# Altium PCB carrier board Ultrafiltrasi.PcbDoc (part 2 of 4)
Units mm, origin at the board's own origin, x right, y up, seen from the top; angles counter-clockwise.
Board outline 196.34 x 220.85 mm, 2 copper layers (Top Layer, Bottom Layer); 114 components, 209 nets, 667 pads, 70 vias.
Unrouted connection lines stored in the file: 5.
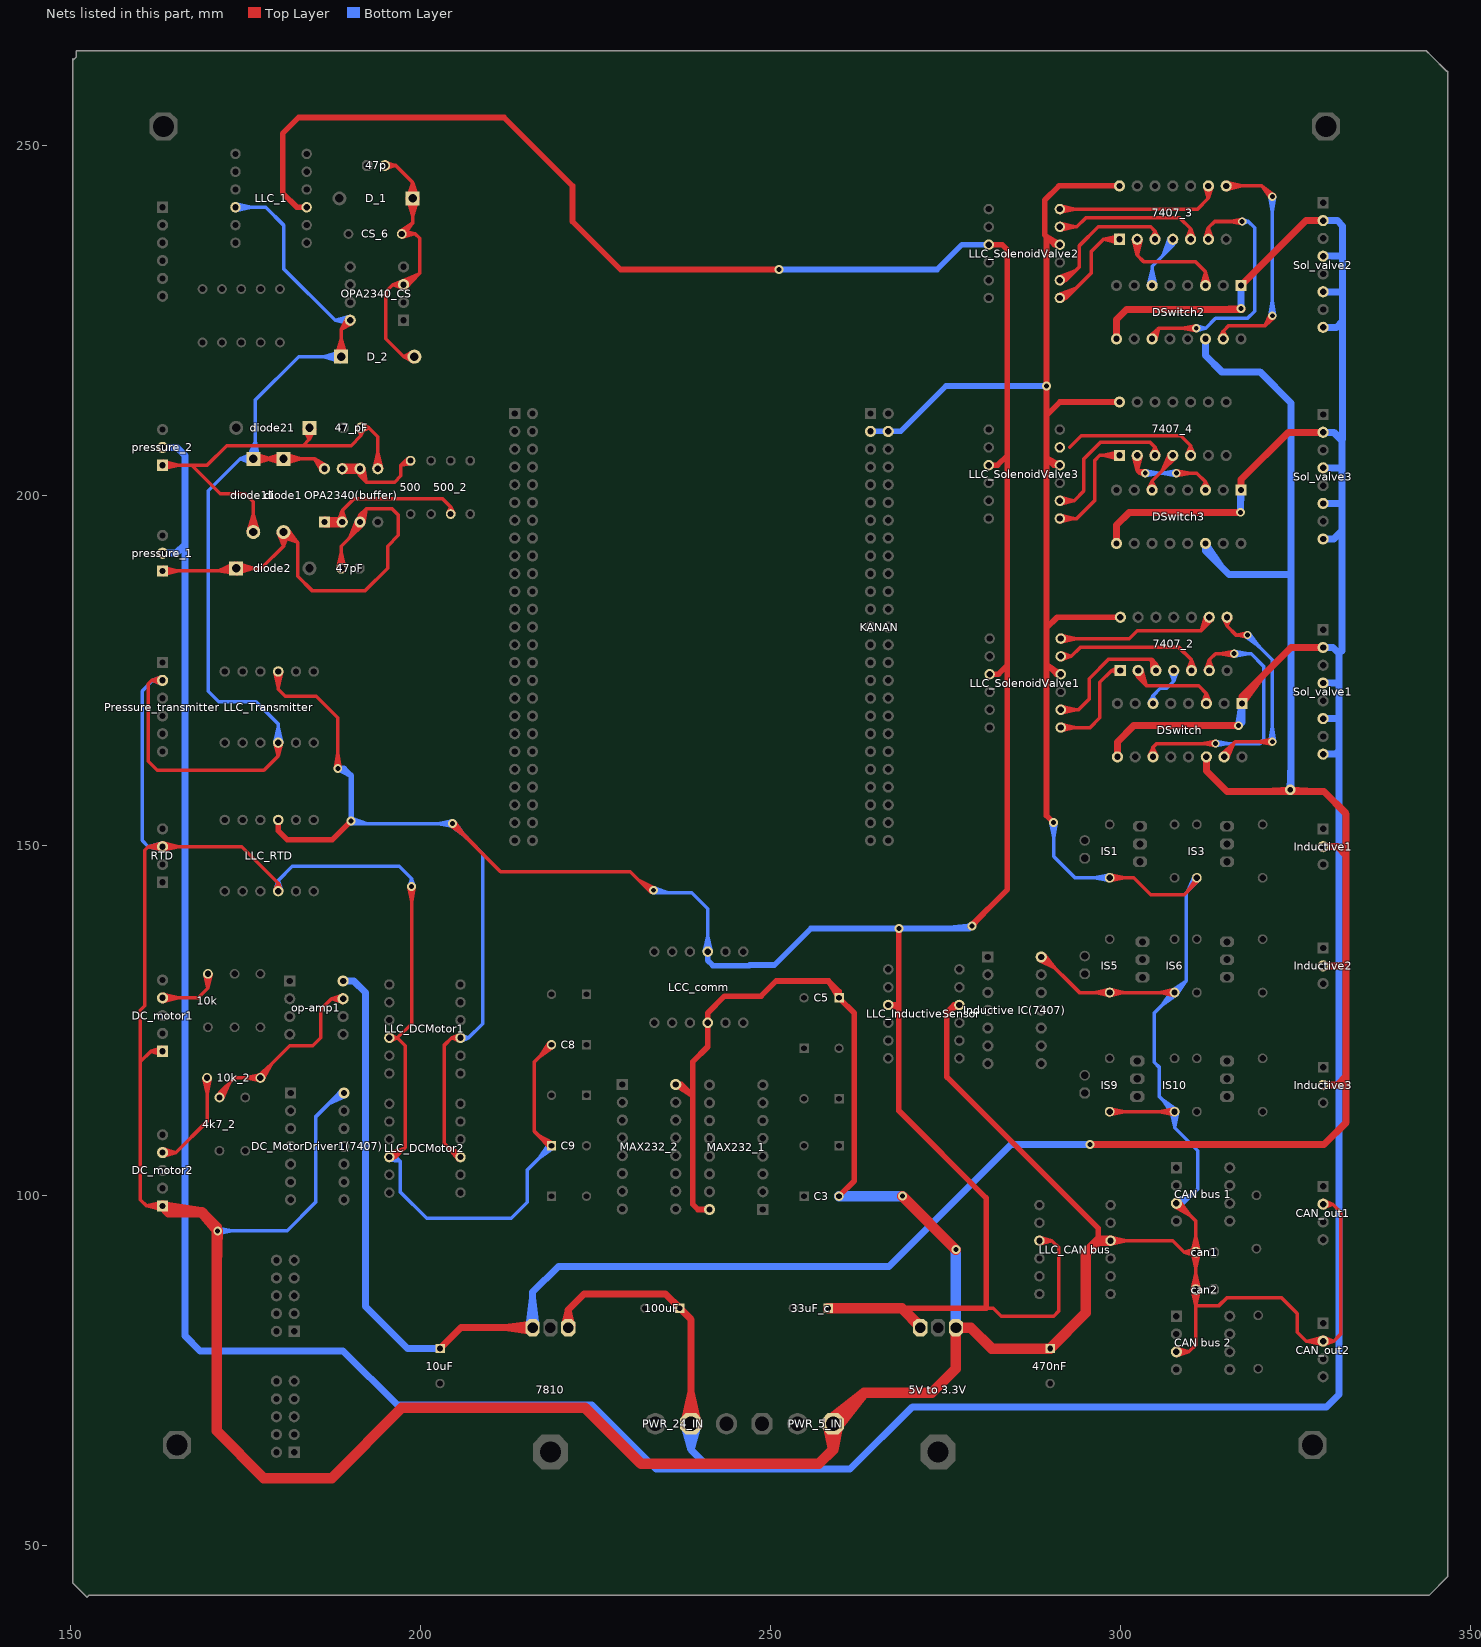
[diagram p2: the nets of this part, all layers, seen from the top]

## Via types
v1: diameter 1.2, hole 0.711, Top Layer to Bottom Layer, 26 vias
v2: diameter 1.27, hole 0.711, Top Layer to Bottom Layer, 24 vias
v3: diameter 1.2, hole 0.7, Top Layer to Bottom Layer, 19 vias
v4: diameter 1.5, hole 0.8, Top Layer to Bottom Layer, 1 vias

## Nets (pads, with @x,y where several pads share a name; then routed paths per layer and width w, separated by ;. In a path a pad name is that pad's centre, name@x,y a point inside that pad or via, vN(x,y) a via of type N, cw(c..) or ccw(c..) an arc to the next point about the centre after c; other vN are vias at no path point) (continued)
Net4k7_2_2: 4k7_2.2 10k_2.1 op-amp1.7 | length 50.9
  Top Layer w0.5: 4k7_2.2@170.978,114.335 172.769,116.127 ; 4k7_2.2@171.714,113.823 172.769,116.127 ; 10k_2.1@176.841,117.152 178.732,118.788 ; 10k_2.1@177.119,116.392 174.965,116.84 10k_2.1@177.119,117.288 ; 10k_2.1@177.54,116.591 178.732,118.788 ; op-amp1.7@188.884,127.601 187.325,128.143 ; op-amp1.7@188.884,128.685 187.325,128.143 ; 172.769,116.127 4k7_2.2@171.323,114.046 171.323,114.681 173.482,116.84 10k_2.1@177.165,116.84 ; 10k_2.1@177.165,116.84 178.732,118.788 ; 10k_2.1@177.165,116.84 177.165,117.221 181.356,121.412 184.658,121.412 185.801,122.555 185.801,126.619 187.325,128.143 ; 187.325,128.143 op-amp1.7@188.976,128.143 187.325,128.143
"Net5V to 3.3V_1": 470nF.1 7407_2.14 7407_3.14 7407_4.14 "5V to 3.3V.1" "CAN bus 1.3" "CAN bus 2.3" "Inductive IC(7407).14" "LLC_CAN bus.P$10" C3.2 C5.1 C8.2 C9.1 can1.2 can2.2 CAN_out1.2 CAN_out2.2 D_2.2 DC_motor1.1 DC_motor2.1 DC_MotorDriver1(7407).14 diode1.2 diode11.2 IS1.1 IS3.1 IS5.1 IS6.1 IS9.1 IS10.1 KANAN.3 KANAN.4 LCC_comm.P$10 LLC_1.P$10 LLC_DCMotor1.P$10 LLC_DCMotor2.P$10 LLC_InductiveSensor.P$10 LLC_RTD.P$10 LLC_SolenoidValve1.P$10 LLC_SolenoidValve2.P$10 LLC_SolenoidValve3.P$10 LLC_Transmitter.P$10 MAX232_1.16 MAX232_2.16 OPA2340(buffer).8 OPA2340_CS.8 Pressure_transmitter.2 PWR_5_IN.1 RTD.3 | length 1543.5
  Top Layer w0.5: Pressure_transmitter.2@163.096,173.068 161.671,173.609 ; Pressure_transmitter.2@163.096,174.15 161.671,173.609 ; DC_motor1.1@163.101,121.192 161.534,120.64 ; DC_motor1.1@163.107,120.107 161.534,120.64 ; RTD.3@163.121,149.315 161.163,149.86 ; RTD.3@163.121,150.405 161.163,149.86 ; DC_motor2.1@163.129,98.006 160.909,98.552 ; DC_motor2.1@163.129,99.098 160.909,98.552 ; DC_motor2.1@163.195,98.552 160.909,98.552 ; DC_motor1.1@163.195,120.64 161.534,120.64 ; DC_motor1.1@163.195,120.65 161.534,120.64 ; Pressure_transmitter.2@163.195,173.609 161.671,173.609 ; RTD.3@163.261,149.314 165.495,149.86 RTD.3@163.261,150.406 ; diode11.2@176.149,205.255 diode1.2@180.467,205.255 184.889,205.255 ; diode11.2@176.161,205.005 178.649,205.255 ; diode11.2@176.161,205.505 178.649,205.255 ; diode11.2@176.262,204.513 178.649,205.255 ; diode11.2@176.262,205.997 178.649,205.255 ; LLC_Transmitter.P$10@179.209,164.653 179.705,162.814 ; LLC_RTD.P$10@179.217,143.619 179.705,144.653 ; LLC_RTD.P$10@179.705,143.51 179.705,144.653 ; LLC_Transmitter.P$10@179.705,164.719 179.705,162.814 ; LLC_RTD.P$10@180.193,143.619 179.705,144.653 ; LLC_Transmitter.P$10@180.201,164.653 179.705,162.814 ; diode1.2@180.354,204.513 177.967,205.255 ; diode1.2@180.354,205.997 177.967,205.255 ; diode1.2@180.455,205.005 177.967,205.255 ; diode1.2@180.455,205.505 177.967,205.255 ; diode1.2@180.479,205.005 182.967,205.255 ; diode1.2@180.479,205.505 182.967,205.255 ; diode1.2@180.58,204.513 182.967,205.255 ; diode1.2@180.58,205.997 182.967,205.255 ; 185.87,203.503 184.889,205.255 ; 186.309,203.835 184.889,205.255 ; 186.641,204.274 184.889,205.255 ; D_2.2@187.957,219.95 188.699,222.337 ; D_2.2@188.449,219.849 188.699,222.337 ; D_2.2@188.699,219.837 188.699,223.751 ; D_2.2@188.949,219.849 188.699,222.337 ; D_2.2@189.441,219.95 188.699,222.337 ; OPA2340_CS.8@189.549,225.37 188.699,223.751 ; OPA2340_CS.8@189.992,225.044 188.699,223.751 ; OPA2340_CS.8@190.318,224.601 188.699,223.751 ; LLC_DCMotor2.P$10@195.369,105.99 197.759,106.827 ; LLC_DCMotor1.P$10@195.58,122.555 196.723,122.555 ; LLC_DCMotor1.P$10@195.689,122.067 196.723,122.555 ; LLC_DCMotor1.P$10@195.689,123.043 196.723,122.555 ; LLC_DCMotor2.P$10@195.876,105.134 197.759,106.827 ; v2@198.372,144.11 198.755,142.01 v2@199.138,144.11 ; v2(198.755,144.145) 198.755,124.587 196.723,122.555 ; C8.2@218.409,121.844 216.998,119.835 C8.2@219.007,121.245 ; C9.1@218.441,106.848 216.835,108.666 ; C8.2@218.734,121.571 216.309,119.146 216.309,109.192 218.345,107.156 C9.1@218.734,107.156 216.835,108.666 ; C9.1@218.968,107.511 216.835,108.666 ; 288.37,133.652 290.717,132.447 ; 289.061,134.5 290.717,132.447 ; IS5.1@298.404,128.584 296.25,129.032 IS5.1@298.404,129.48 ; IS9.1@298.45,112.014 IS10.1@307.721,112.014 ; IS1.1@298.45,145.415 301.879,145.415 304.292,143.002 309.118,143.002 310.896,144.78 IS3.1@310.896,145.415 309.468,143.352 IS3.1@311.242,145.127 ; IS9.1@298.496,111.566 300.65,112.014 IS9.1@298.496,112.462 ; IS5.1@298.496,128.584 300.65,129.032 IS5.1@298.496,129.48 ; IS1.1@298.496,144.967 300.65,145.415 IS1.1@298.496,145.863 ; 298.577,93.599 307.467,93.599 309.118,91.948 ; 298.633,93.102 300.827,93.599 298.633,94.096 ; 307.66,98.482 309.933,97.229 ; IS10.1@307.675,111.566 305.521,112.014 IS10.1@307.675,112.462 ; IS6.1@307.675,128.584 305.521,129.032 IS6.1@307.675,129.48 ; IS6.1@307.721,129.032 IS5.1@298.45,129.032 294.132,129.032 289.052,134.112 288.671,134.112 290.717,132.447 ; 307.975,77.724 309.753,77.724 ; 308.06,77.181 309.753,77.724 ; 308.06,78.267 309.753,77.724 ; 308.378,99.307 309.933,97.229 ; can2.2@310.26,86.556 310.769,84.352 can2.2@311.278,86.556 ; can2.2@310.26,86.672 310.769,88.876 can2.2@311.278,86.672 ; can1.2@310.26,91.89 310.769,89.686 can1.2@311.278,91.89 ; can1.2@310.26,92.006 310.769,94.21 can1.2@311.278,92.006 ; can1.2@310.69,91.442 309.118,91.948 ; can1.2@310.69,92.454 309.118,91.948 ; CAN_out2.2@328.864,78.702 326.63,79.248 CAN_out2.2@328.864,79.794 ; CAN_out1.2@328.93,98.806 330.327,98.806 ; CAN_out2.2@329.029,78.707 330.454,79.248 ; CAN_out2.2@329.029,79.789 330.454,79.248 ; CAN_out1.2@329.038,98.267 330.327,98.806 ; CAN_out1.2@329.038,99.345 330.327,98.806 ; 160.02,119.126 160.02,126.512 160.645,127.137 160.645,149.342 161.163,149.86 ; 160.02,119.126 160.02,99.441 160.909,98.552 ; 160.02,119.126 161.534,120.64 ; 161.163,149.86 RTD.3@163.195,149.86 174.498,149.86 179.705,144.653 ; 161.671,173.609 161.163,173.101 161.163,162.052 162.433,160.782 177.673,160.782 179.705,162.814 ; LLC_DCMotor2.P$10@195.58,105.537 196.469,105.537 ; LLC_DCMotor2.P$10@195.58,105.537 197.759,106.827 ; LLC_DCMotor2.P$10@195.58,105.537 196.469,105.537 ; 196.469,105.537 195.721,105.057 196.469,105.537 ; 196.469,105.537 195.721,106.017 196.469,105.537 ; 196.469,105.537 197.866,106.934 197.866,121.412 196.723,122.555 ; 309.118,91.948 can1.2@310.769,91.948 ; 309.753,77.724 310.769,78.74 310.769,84.328 ; 309.933,97.229 307.975,98.933 308.229,98.933 310.769,96.393 can1.2@310.769,91.948 ; 310.769,84.328 314.071,84.328 315.214,85.471 322.961,85.471 325.247,83.185 325.247,80.518 326.517,79.248 CAN_out2.2@328.93,79.248 330.454,79.248 ; 310.769,84.328 can2.2@310.769,86.614 can1.2@310.769,91.948 ; 330.327,98.806 331.47,97.663 331.47,80.264 330.454,79.248
  Top Layer w0.8: 241.046,121.564 LCC_comm.P$10@241.046,124.714 ; C3.2@259.802,99.949 262.001,102.148 262.001,126.071 C5.1@259.802,128.27 ; v2(290.449,153.289) 289.433,154.305 289.433,175.895 ; LLC_SolenoidValve1.P$10@290.83,174.498 289.433,175.895 ; LLC_SolenoidValve1.P$10@291.465,174.498 289.433,175.895 ; 296.799,93.599 296.799,95.377 275.209,116.967 275.209,126.238 ; 7407_4.14@299.847,213.36 291.338,213.36 289.433,211.455 ; 7407_3.14@299.847,244.221 291.211,244.221 289.179,242.189 289.179,237.236 289.433,236.982 ; 7407_2.14@299.974,182.626 290.957,182.626 289.433,181.102 ; MAX232_2.16@236.474,115.892 237.295,115.892 ; MAX232_2.16@236.474,115.892 238.887,114.3 ; MAX232_2.16@236.474,115.892 237.295,115.892 ; 237.295,115.892 238.887,114.3 ; 238.887,114.3 238.887,98.806 239.649,98.044 ; 238.887,114.3 238.887,119.126 241.046,121.285 LCC_comm.P$10@241.046,124.714 ; 239.649,98.044 MAX232_1.16@241.3,98.044 239.649,98.044 ; LCC_comm.P$10@241.046,124.714 241.046,126.111 243.459,128.524 248.666,128.524 250.825,130.683 258.318,130.683 ; 258.318,130.683 C5.1@259.802,128.27 ; 258.318,130.683 259.802,129.199 ; C5.1@259.802,128.27 259.802,129.199 ; C5.1@259.802,128.27 259.802,129.199 ; 275.209,126.238 LLC_InductiveSensor.P$10@276.987,127.254 ; 275.209,126.238 276.225,127.254 ; 276.225,127.254 LLC_InductiveSensor.P$10@276.987,127.254 ; 276.225,127.254 LLC_InductiveSensor.P$10@276.987,127.254 ; 289.433,175.895 289.433,181.102 ; 289.433,181.102 289.433,205.359 ; 289.433,205.359 LLC_SolenoidValve3.P$10@291.338,204.343 ; 289.433,205.359 290.449,204.343 ; 289.433,205.359 289.433,211.455 ; 289.433,211.455 289.433,236.982 ; 289.433,236.982 LLC_SolenoidValve2.P$10@291.338,235.839 ; 289.433,236.982 290.576,235.839 ; 290.449,204.343 LLC_SolenoidValve3.P$10@291.338,204.343 ; 290.449,204.343 LLC_SolenoidValve3.P$10@291.338,204.343 ; 290.576,235.839 LLC_SolenoidValve2.P$10@291.338,235.839 ; 290.576,235.839 LLC_SolenoidValve2.P$10@291.338,235.839
  Top Layer w1.5: 170.942,89.854 v2(171.069,94.996) 168.783,97.663 ; PWR_5_IN.1@258.196,67.368 258.966,63.767 ; PWR_5_IN.1@258.453,68.03 263.398,71.882 ; PWR_5_IN.1@259.546,66.937 263.398,71.882 ; PWR_5_IN.1@259.735,67.368 258.966,63.767 ; v2(268.859,99.949) v2(276.492,92.316) ; 276.492,75.396 276.492,80.912 ; 298.577,93.599 296.799,93.599 295.021,91.821 295.021,83.272 470nF.1@289.941,78.192 281.599,78.192 278.625,81.166 276.492,81.166 276.492,75.324 273.05,71.882 263.398,71.882 ; DC_motor2.1@163.195,98.552 164.084,97.663 ; DC_motor2.1@163.195,98.552 168.783,97.663 ; DC_motor2.1@163.195,98.552 164.084,97.663 ; 164.084,97.663 168.783,97.663 ; 168.783,97.663 170.942,95.504 170.942,66.421 177.673,59.69 187.325,59.69 197.358,69.723 223.52,69.723 231.521,61.722 256.921,61.722 258.966,63.767 ; 258.966,63.767 PWR_5_IN.1@258.966,67.45 263.398,71.882
  Bottom Layer w0.5: Pressure_transmitter.2@163.087,173.07 161.798,173.609 ; Pressure_transmitter.2@163.087,174.148 161.798,173.609 ; RTD.3@163.121,149.315 161.163,149.86 ; RTD.3@163.121,150.405 161.163,149.86 ; RTD.3@163.195,149.86 161.163,149.86 ; Pressure_transmitter.2@163.195,173.609 161.798,173.609 ; v2@170.688,94.996 180.975,94.996 185.039,99.06 185.039,111.259 188.171,114.391 ; v2(171.069,94.996) 173.204,94.996 ; v2@171.104,94.613 173.204,94.996 ; v2@171.104,95.379 173.204,94.996 ; LLC_1.P$10@173.609,241.173 177.927,241.173 180.467,238.633 180.467,232.41 187.833,225.044 ; LLC_1.P$10@173.665,240.676 175.859,241.173 LLC_1.P$10@173.665,241.67 ; diode11.2@175.426,205.454 176.463,207.809 ; diode11.2@175.903,205.298 176.463,207.809 ; diode11.2@176,204.52 174.267,205.255 ; diode11.2@176,205.99 174.267,205.255 ; diode11.2@176.132,205.006 174.267,205.255 ; diode11.2@176.132,205.504 174.267,205.255 ; diode11.2@176.398,205.237 176.463,207.809 ; diode11.2@176.899,205.273 176.463,207.809 ; LLC_Transmitter.P$10@179.208,164.775 179.705,166.969 LLC_Transmitter.P$10@180.202,164.775 ; LLC_RTD.P$10@179.212,143.592 179.705,145.034 ; LLC_RTD.P$10@179.705,143.51 179.705,145.034 ; LLC_Transmitter.P$10@179.705,164.719 179.705,167.386 176.53,170.561 171.196,170.561 169.725,172.032 169.725,200.713 174.267,205.255 ; LLC_RTD.P$10@180.198,143.592 179.705,145.034 ; D_2.2@188.586,219.095 186.199,219.837 ; D_2.2@188.586,220.579 186.199,219.837 ; D_2.2@188.686,219.587 186.199,219.837 ; D_2.2@188.686,220.087 186.199,219.837 ; D_2.2@188.699,219.837 182.626,219.837 176.463,213.674 176.463,205.569 diode11.2@176.149,205.255 ; 188.742,115.096 186.941,113.161 ; 189.371,114.201 186.941,113.161 ; OPA2340_CS.8@189.922,224.498 187.833,225.044 ; OPA2340_CS.8@189.922,225.59 187.833,225.044 ; OPA2340_CS.8@189.992,225.044 187.833,225.044 ; LLC_DCMotor2.P$10@195.46,105.052 197.104,104.902 ; LLC_DCMotor2.P$10@195.84,105.964 197.104,104.902 ; v2@198.375,144.21 198.755,145.288 ; v2(198.755,144.145) 198.755,145.288 ; v2@199.135,144.21 198.755,145.288 ; C9.1@218.409,107.43 216.998,105.421 C9.1@219.007,106.831 ; C9.1@218.734,107.156 215.265,103.687 215.265,99.06 212.979,96.774 200.914,96.774 197.104,100.584 197.104,104.902 ; v2@290.066,153.254 290.449,151.154 v2@290.832,153.254 ; v2(290.449,153.289) 290.449,148.463 293.497,145.415 IS1.1@298.45,145.415 ; IS1.1@298.404,144.967 296.25,145.415 IS1.1@298.404,145.863 ; IS10.1@307.273,111.968 307.721,109.814 IS10.1@308.169,111.968 ; IS10.1@307.375,111.726 305.96,113.775 IS10.1@308.009,112.36 ; IS6.1@307.375,129.32 305.96,127.271 IS6.1@308.009,128.686 ; IS6.1@307.435,129.379 309.372,130.683 ; 307.755,99.437 310.308,100.25 ; IS6.1@308.068,128.746 309.372,130.683 ; 308.293,98.484 310.308,100.25 ; IS3.1@310.504,145.636 309.483,143.367 ; IS3.1@311.242,145.127 309.483,143.367 ; 161.163,149.86 160.274,150.749 160.274,172.085 161.798,173.609 ; 174.267,205.255 diode11.2@176.149,205.255 ; diode11.2@176.149,205.255 176.463,207.809 ; 179.705,145.034 181.737,147.066 196.977,147.066 198.755,145.288 ; 186.941,113.161 189.103,114.681 ; 188.171,114.391 189.103,114.681 ; 188.171,114.391 188.798,115.139 188.171,114.391 ; 188.171,114.391 189.112,114.131 188.171,114.391 ; 188.171,114.391 189.103,114.681 ; 188.171,114.391 188.813,114.391 189.103,114.681 ; LLC_DCMotor2.P$10@195.58,105.537 196.469,105.537 ; LLC_DCMotor2.P$10@195.58,105.537 197.104,104.902 ; LLC_DCMotor2.P$10@195.58,105.537 196.469,105.537 ; 196.469,105.537 195.721,105.057 196.469,105.537 ; 196.469,105.537 195.721,106.017 196.469,105.537 ; 196.469,105.537 197.104,104.902 ; 307.975,98.933 308.991,98.933 ; 307.975,98.933 310.308,100.25 ; 307.975,98.933 308.991,98.933 ; 308.991,98.933 308.124,98.404 308.991,98.933 ; 308.991,98.933 308.124,99.462 308.991,98.933 ; 308.991,98.933 311.023,100.965 311.023,106.426 307.721,109.728 IS10.1@307.721,112.014 305.562,114.173 305.562,118.328 304.8,119.09 304.8,126.111 IS6.1@307.721,129.032 309.372,130.683 ; 309.372,130.683 309.372,143.256 310.896,144.78 IS3.1@310.896,145.415 309.483,143.367
  Bottom Layer w0.8: KANAN.3@264.287,209.169 KANAN.4@266.827,209.169 268.605,209.169 275.082,215.646 v2(289.433,215.646)
  Bottom Layer w1.5: C3.2@259.802,99.949 v2(268.859,99.949) 263.724,99.949 ; 276.492,81.166 v2(276.492,92.316) 276.492,87.181 ; 276.492,81.42 276.492,86.936
"Net5V to 3.3V_3": 33uF_c.1 "5V to 3.3V.3" "LLC_CAN bus.P$3" LCC_comm.P$3 LLC_1.P$3 LLC_DCMotor1.P$3 LLC_DCMotor2.P$3 LLC_InductiveSensor.P$3 LLC_RTD.P$3 LLC_SolenoidValve1.P$3 LLC_SolenoidValve2.P$3 LLC_SolenoidValve3.P$3 LLC_Transmitter.P$3 | length 630.4
  Top Layer w0.5: LLC_Transmitter.P$3@179.208,174.823 179.705,172.629 LLC_Transmitter.P$3@180.202,174.823 ; LLC_Transmitter.P$3@179.705,174.879 179.705,172.339 180.697,171.347 185.142,171.347 188.214,168.275 v2(188.214,161.036) ; v2@187.831,161.071 188.214,163.171 v2@188.597,161.071 ; v2@204.347,152.869 206.293,151.466 v2@204.89,153.412 ; v2(204.597,153.162) 211.455,146.304 229.997,146.304 v2@232.981,143.32 ; LLC_DCMotor2.P$3@205.389,105.181 203.785,107.111 ; LLC_DCMotor1.P$3@205.642,122.065 204.47,122.555 ; LLC_DCMotor1.P$3@205.642,123.045 204.47,122.555 ; LLC_DCMotor1.P$3@205.74,122.555 204.47,122.555 ; LLC_DCMotor2.P$3@206.013,105.956 203.785,107.111 ; v2@233.057,143.337 231.292,145.009 ; v2(233.299,143.637) 231.292,145.009 ; v2@233.49,143.971 231.292,145.009 ; 280.797,83.947 281.813,83.947 282.956,82.804 290.449,82.804 291.211,83.566 291.211,92.583 290.195,93.599 ; 288.417,93.599 290.195,93.599 ; 288.487,93.104 290.195,93.599 ; 288.487,94.094 290.195,93.599 ; 203.785,107.111 LLC_DCMotor2.P$3@205.74,105.537 205.359,105.537 203.454,107.442 203.454,121.539 204.47,122.555
  Top Layer w0.8: LLC_RTD.P$3@179.705,153.67 179.705,152.146 180.975,150.876 187.452,150.876 v2(190.119,153.543) ; LLC_1.P$3@183.769,241.173 182.372,241.173 180.34,243.205 180.34,251.714 182.626,254 211.963,254 221.742,244.221 221.742,239.141 228.6,232.283 v2(251.206,232.283) 248.171,232.283 ; v2(268.351,138.176) 268.351,126.873 ; 268.732,83.947 280.797,83.947 280.797,99.695 268.351,112.141 268.351,126.873 ; v2@278.511,138.43 283.845,143.764 283.845,175.768 ; v2(278.765,138.557) 281.028,140.947 ; LLC_SolenoidValve3.P$3@281.178,204.343 282.448,204.343 283.845,205.74 ; LLC_SolenoidValve2.P$3@281.178,235.839 283.083,235.839 283.845,235.077 283.845,205.74 ; LLC_SolenoidValve1.P$3@281.305,174.498 282.575,174.498 283.845,175.768 ; LLC_InductiveSensor.P$3@266.827,127.254 267.97,127.254 ; LLC_InductiveSensor.P$3@266.827,127.254 268.351,126.873 ; LLC_InductiveSensor.P$3@266.827,127.254 267.97,127.254 ; 267.97,127.254 268.351,126.873 ; 283.845,175.768 283.845,205.74
  Top Layer w1.5: 33uF_c.1@258.278,83.947 268.732,83.947 ; 271.412,81.166 271.412,81.267 268.732,83.947 ; 271.412,81.42 268.732,83.947
  Bottom Layer w0.5: v2@190.088,153.159 192.444,153.162 ; v2@190.212,153.917 192.444,153.162 ; v2@204.347,152.869 206.293,151.466 v2@204.89,153.412 ; v2@204.562,152.779 202.462,153.162 v2@204.562,153.545 ; LLC_DCMotor1.P$3@205.74,122.555 206.883,122.555 ; LLC_DCMotor1.P$3@205.849,122.067 206.883,122.555 ; LLC_DCMotor1.P$3@205.849,123.043 206.883,122.555 ; v2@233.267,143.253 235.518,143.256 ; v2@233.299,143.256 238.76,143.256 241.046,140.97 LCC_comm.P$3@241.046,134.874 ; v2(233.299,143.637) 235.518,143.256 ; v2@233.396,144.009 235.518,143.256 ; LCC_comm.P$3@240.549,134.93 241.046,137.124 LCC_comm.P$3@241.543,134.93 ; 192.444,153.162 v2(190.119,153.543) 190.5,153.162 v2(204.597,153.162) 208.915,148.844 208.915,124.587 206.883,122.555
  Bottom Layer w0.8: v2(190.119,153.543) 190.119,160.02 ; LCC_comm.P$3@241.046,134.874 241.046,133.604 241.786,132.864 246.958,132.864 247.063,132.969 250.571,132.969 255.778,138.176 v2(268.351,138.176) 278.384,138.176 v2(278.765,138.557) 275.545,138.176 ; v2(251.206,232.283) 273.812,232.283 277.368,235.839 LLC_SolenoidValve2.P$3@281.178,235.839 ; v2(188.214,161.036) 189.103,161.036 ; v2(188.214,161.036) 190.119,160.02 ; v2(188.214,161.036) 189.103,161.036 ; 189.103,161.036 190.119,160.02
Net10k_2: 10k.2 DC_motor1.4 | length 19.8
  Top Layer w0.5: DC_motor1.4@163.195,128.27 168.275,128.27 169.672,129.667 ; DC_motor1.4@163.261,127.724 165.495,128.27 DC_motor1.4@163.261,128.816 ; 10k.2@169.225,131.649 169.672,129.667 ; 10k.2@170.119,131.649 169.672,129.667 ; 169.672,129.667 10k.2@169.672,131.699 169.672,129.667
Net10k_2_2: 10k_2.2 DC_motor2.4 | length 22.6
  Top Layer w0.5: DC_motor2.4@163.195,106.172 165.1,106.172 ; DC_motor2.4@163.274,105.628 165.1,106.172 ; DC_motor2.4@163.274,106.716 165.1,106.172 ; 10k_2.2@169.097,116.794 169.545,114.64 10k_2.2@169.993,116.794 ; 10k_2.2@169.545,116.84 169.545,110.617 165.1,106.172
Net10uF_1: 10uF.1 7810.3 DSwitch2.14 DSwitch3.14 DSwitch.14 Inductive1.2 Inductive2.2 Inductive3.2 op-amp1.8 | length 413.6
  Top Layer w1: 10uF.1@202.819,78.192 205.793,81.166 7810.3@216.04,81.166 ; 7810.3@216.007,80.651 212.024,81.166 7810.3@216.007,81.681 ; v2(295.656,107.315) 329.057,107.315 332.232,110.49 332.232,117.094 ; DSwitch.14@312.254,162.687 312.254,160.694 315.214,157.734 329.057,157.734 332.232,154.559 332.232,148.59 ; 320.446,157.734 v4(324.231,157.988) 328.011,157.734 ; Inductive3.2@328.93,115.824 330.962,115.824 332.232,117.094 ; Inductive2.2@328.93,132.842 332.105,132.842 ; Inductive1.2@328.93,149.86 330.962,149.86 332.232,148.59 ; 332.232,117.094 332.232,148.59
  Bottom Layer w1: op-amp1.8@188.976,130.683 190.5,130.683 192.151,129.032 192.151,84.201 198.16,78.192 10uF.1@202.819,78.192 ; 7810.3@215.525,81.453 216.04,85.436 ; 7810.3@216.04,81.166 216.04,86.246 219.71,89.916 266.954,89.916 284.353,107.315 v2(295.656,107.315) ; 7810.3@216.04,81.42 216.04,85.436 ; 7810.3@216.555,81.453 216.04,85.436 ; 314.53,189.66 DSwitch3.14@312.127,193.167 ; v4(324.231,157.988) 324.358,161.75 ; v4@324.231,158.242 324.358,158.115 324.358,188.722 ; 312.127,192.063 DSwitch3.14@312.127,193.167 ; 312.127,192.063 315.468,188.722 324.358,188.722 ; 312.127,192.063 DSwitch3.14@312.127,193.167 ; 312.127,220.003 DSwitch2.14@312.127,222.377 312.127,220.003 ; 312.127,220.003 314.452,217.678 319.913,217.678 324.358,213.233 324.358,188.722
Net47_pF_2: 47_pF.2 diode11.1 diode21.2 OPA2340(buffer).5 pressure_2.1 | length 98.8
  Top Layer w0.5: pressure_2.1@163.195,204.343 167.386,204.343 ; pressure_2.1@163.261,203.797 165.495,204.343 pressure_2.1@163.261,204.889 ; diode11.1@175.407,194.907 176.149,197.295 ; diode11.1@175.899,194.807 176.149,197.295 ; diode11.1@176.149,194.795 176.149,199.136 175.006,200.279 171.45,200.279 167.386,204.343 ; diode11.1@176.399,194.807 176.149,197.295 ; diode11.1@176.891,194.907 176.149,197.295 ; 47_pF.2@191.017,209.562 191.516,208.534 ; 47_pF.2@191.631,209.178 192.659,209.677 ; 47_pF.2@191.631,210.176 192.659,209.677 ; 47_pF.2@192.015,209.562 191.516,208.534 ; 193.383,203.901 193.929,206.135 194.475,203.901 ; 193.929,203.835 193.929,208.407 192.659,209.677 ; 167.386,204.343 169.545,204.343 172.339,207.137 183.261,207.137 ; 183.261,207.137 190.119,207.137 191.516,208.534 ; 183.261,207.137 184.15,208.026 ; 184.15,208.026 diode21.2@184.173,209.677 184.15,208.026 ; 184.15,208.026 183.923,209.662 184.15,208.026 ; 184.15,208.026 184.422,209.655 184.15,208.026 ; 184.15,208.026 183.44,209.517 184.15,208.026 ; 184.15,208.026 184.901,209.497 184.15,208.026 ; 184.15,208.026 184.15,209.677 184.15,208.026 ; 191.516,208.534 47_pF.2@191.516,209.677 192.659,209.677
Net47p_2: 47p.2 CS_6.2 D_1.2 D_2.1 OPA2340_CS.3 | length 85.8
  Top Layer w0.5: 47p.2@194.945,247.142 196.469,247.142 ; 47p.2@195.031,246.637 196.469,247.142 ; 47p.2@195.031,247.647 196.469,247.142 ; CS_6.2@197.074,237.712 198.905,238.91 ; OPA2340_CS.3@197.346,230.605 199.733,231.61 ; CS_6.2@197.411,236.916 199.263,237.363 ; CS_6.2@197.411,237.81 199.263,237.363 ; OPA2340_CS.3@197.513,229.583 196.088,230.124 ; OPA2340_CS.3@197.513,230.665 196.088,230.124 ; CS_6.2@197.707,237.079 198.905,238.91 ; OPA2340_CS.3@197.974,229.71 199.733,231.61 ; D_1.2@198.163,242.33 198.905,239.943 ; D_1.2@198.165,242.567 198.905,244.706 ; D_1.2@198.655,242.431 198.905,239.943 ; D_1.2@198.655,242.457 198.905,244.706 ; D_2.1@198.977,219.109 197.612,219.837 ; D_2.1@198.977,220.565 197.612,219.837 ; D_2.1@199.139,219.588 197.612,219.837 ; D_2.1@199.139,220.086 197.612,219.837 ; D_1.2@199.155,242.431 198.905,239.943 ; D_1.2@199.155,242.457 198.905,244.706 ; D_2.1@199.159,219.837 197.612,219.837 ; D_1.2@199.645,242.567 198.905,244.706 ; D_1.2@199.647,242.33 198.905,239.943 ; 196.088,230.124 OPA2340_CS.3@197.612,230.124 ; 196.088,230.124 195.072,229.108 195.072,222.377 197.612,219.837 ; 196.469,247.142 198.905,244.706 ; OPA2340_CS.3@197.612,230.124 199.733,231.61 ; OPA2340_CS.3@197.612,230.124 198.247,230.124 199.898,231.775 199.898,236.728 199.263,237.363 ; 198.905,238.91 D_1.2@198.905,242.443 198.905,244.706 ; 198.905,238.91 CS_6.2@197.358,237.363 199.263,237.363
Net47pF_2: 47pF.2 diode1.1 diode2.2 OPA2340(buffer).3 pressure_1.1 | length 138.8
  Top Layer w0.5: pressure_1.1@163.195,189.23 173.332,189.23 diode2.2@173.713,189.611 ; pressure_1.1@163.261,188.684 165.495,189.23 pressure_1.1@163.261,189.776 ; diode2.2@173.499,190.33 171.123,189.23 ; diode2.2@173.665,189.856 171.123,189.23 ; diode2.2@173.715,188.861 171.123,189.23 ; diode2.2@173.725,189.361 176.213,189.611 ; diode2.2@173.725,189.861 176.213,189.611 ; diode2.2@173.738,189.362 171.123,189.23 ; diode2.2@173.825,188.869 176.213,189.611 ; diode2.2@173.825,190.353 176.213,189.611 ; diode1.1@179.73,194.655 180.467,192.786 ; diode1.1@180.116,194.132 182.499,193.294 ; diode1.1@180.217,194.779 180.467,192.786 ; diode1.1@180.329,194.587 182.499,193.294 ; diode1.1@180.625,194.988 182.499,193.294 ; diode1.1@180.717,194.779 180.467,192.786 ; diode1.1@180.997,195.325 182.499,193.294 ; diode1.1@181.204,194.655 180.467,192.786 ; 47pF.2@188.213,189.669 188.722,191.873 47pF.2@189.231,189.669 ; 47pF.2@188.722,189.611 188.722,192.786 191.389,195.453 191.389,196.215 ; 190.902,196.471 189.888,193.952 ; 190.925,196.511 192.278,198.12 ; 191.814,195.866 189.888,193.952 ; 191.914,196.05 192.278,198.12 ; 171.123,189.23 diode2.2@173.713,189.611 ; diode2.2@173.713,189.611 177.292,189.611 180.467,192.786 ; 180.467,192.786 diode1.1@180.467,194.795 ; diode1.1@180.467,194.795 182.499,193.294 ; diode1.1@180.467,194.795 180.998,194.795 182.499,193.294 ; 182.499,193.294 182.499,188.468 184.531,186.436 192.151,186.436 195.326,189.611 195.326,192.786 196.85,194.31 196.85,197.231 195.961,198.12 192.278,198.12 ; 189.888,193.952 191.389,196.215 ; 191.389,196.215 191.389,197.231 ; 191.389,196.215 192.278,198.12 ; 191.389,196.215 191.389,197.231 ; 191.389,197.231 191.918,196.364 191.389,197.231 ; 191.389,197.231 190.86,196.364 191.389,197.231 ; 191.389,197.231 192.278,198.12
Net100uF_1: 100uF.1 7810.1 DSwitch2.1 DSwitch2.9 DSwitch3.1 DSwitch3.9 DSwitch.1 DSwitch.9 pressure_1.2 pressure_2.2 PWR_24_IN.1 Sol_valve1.2 Sol_valve1.4 Sol_valve1.6 Sol_valve1.8 Sol_valve2.2 Sol_valve2.4 Sol_valve2.6 Sol_valve2.8 Sol_valve3.2 Sol_valve3.4 Sol_valve3.6 Sol_valve3.8 | length 718.7
  Top Layer w1: 7810.1@220.607,81.478 221.12,83.706 ; 7810.1@221.12,81.166 221.12,83.706 ; 7810.1@221.12,81.42 221.12,83.706 ; 7810.1@221.632,81.478 221.12,83.706 ; PWR_24_IN.1@237.628,67.566 238.646,71.974 PWR_24_IN.1@239.663,67.566 ; PWR_24_IN.1@238.646,67.45 238.646,82.37 100uF.1@237.069,83.947 235.037,85.979 223.393,85.979 221.12,83.706 ; DSwitch3.9@299.427,193.167 299.427,195.795 301.244,197.612 v2(317.119,197.612) ; DSwitch2.9@299.427,222.377 299.427,225.132 300.863,226.568 v2@317.373,226.568 ; DSwitch.9@299.554,162.687 299.554,164.807 301.879,167.132 v2(316.865,167.132) ; 313.556,226.568 v2(317.207,226.734) ; DSwitch3.1@317.207,200.787 317.207,202.272 323.977,209.042 Sol_valve3.2@328.93,209.042 Sol_valve3.2@329.184,209.042 ; DSwitch2.1@317.207,229.997 326.478,239.268 ; 319.837,173.787 DSwitch.1@317.334,170.307 ; Sol_valve2.2@328.803,239.268 326.478,239.268 ; Sol_valve1.2@328.93,178.308 324.358,178.308 317.334,171.284 ; Sol_valve2.2@328.93,239.268 326.478,239.268 ; DSwitch.1@317.334,170.307 317.334,171.284 ; DSwitch.1@317.334,170.307 317.334,171.284
  Bottom Layer w1: pressure_1.2@163.195,191.77 165.1,191.77 166.37,193.04 ; pressure_2.2@163.195,206.883 165.227,206.883 166.37,205.74 166.37,193.04 ; PWR_24_IN.1@237.632,67.308 238.646,63.741 ; PWR_24_IN.1@238.646,67.45 238.646,63.741 ; PWR_24_IN.1@239.66,67.308 238.646,63.741 ; Sol_valve1.8@328.93,163.068 330.708,163.068 331.216,163.576 ; Sol_valve1.6@328.93,168.148 331.089,168.148 ; Sol_valve1.4@328.93,173.228 331.216,173.228 ; Sol_valve1.2@328.93,178.308 330.327,178.308 331.216,177.419 331.216,173.228 ; Sol_valve3.8@328.93,193.802 330.454,193.802 331.597,194.945 ; Sol_valve3.6@328.93,198.882 331.597,198.882 ; Sol_valve3.4@328.93,203.962 331.597,203.962 ; Sol_valve3.2@328.93,209.042 330.454,209.042 331.597,207.899 331.597,203.962 ; Sol_valve2.8@328.93,224.028 330.835,224.028 331.724,224.917 ; Sol_valve2.6@328.93,229.108 331.724,229.108 ; Sol_valve2.4@328.93,234.188 331.597,234.188 ; Sol_valve2.2@328.93,239.268 330.962,239.268 331.724,238.506 331.724,229.108 ; 331.597,177.8 331.597,194.945 ; 331.724,208.026 331.724,224.917 ; 166.37,193.04 166.37,80.01 168.529,77.851 188.976,77.851 196.723,70.104 224.536,70.104 233.68,60.96 241.427,60.96 ; 238.646,63.741 241.427,60.96 ; 241.427,60.96 261.366,60.96 270.256,69.85 329.438,69.85 331.216,71.628 331.216,163.576 ; 331.216,163.576 331.216,173.228 ; 331.597,194.945 331.597,198.882 ; 331.597,198.882 331.597,203.962 ; 331.724,224.917 331.724,229.108 ; v2(316.865,167.132) DSwitch.1@317.334,170.307 317.334,167.601 v2(316.865,167.132) ; v2(317.119,197.612) DSwitch3.1@317.207,200.787 317.119,200.699 v2(317.119,197.612) ; v2(317.207,226.734) DSwitch2.1@317.207,229.997 v2(317.207,226.734)
Net500_2: 500.2 OPA2340(buffer).6 OPA2340(buffer).7 | length 57.4
  Top Layer w0.5: 188.796,203.288 191.116,203.339 ; 188.796,204.382 191.116,204.331 ; 188.915,203.289 191.149,203.835 188.915,204.381 ; 189.029,203.315 191.116,204.331 ; 189.029,204.355 191.116,203.339 ; 190.925,203.539 192.278,201.93 ; 191.323,203.289 189.089,203.835 191.323,204.381 ; 191.914,204 192.278,201.93 ; 500.2@198.384,205.356 197.231,204.343 ; 500.2@198.752,204.545 197.231,204.343 ; 500.2@199.009,204.978 197.866,204.978 ; 188.849,203.835 191.116,203.339 ; 188.849,203.835 191.116,204.331 ; 188.849,203.835 191.389,203.835 ; 191.389,202.819 190.86,203.686 191.389,202.819 ; 191.389,202.819 191.918,203.686 191.389,202.819 ; 191.389,202.819 191.389,203.835 ; 191.389,202.819 192.278,201.93 ; 191.389,202.819 191.389,203.835 ; 191.389,203.835 192.278,201.93 ; 192.278,201.93 196.342,201.93 197.231,202.819 197.231,204.343 ; 197.231,204.343 500.2@198.628,204.978 ; 197.231,204.343 197.866,204.978 ; 197.866,204.978 500.2@198.628,204.978 ; 197.866,204.978 198.495,205.408 197.866,204.978 ; 197.866,204.978 198.495,204.548 197.866,204.978 ; 197.866,204.978 500.2@198.628,204.978
Net500_2_2: 500_2.2 OPA2340(buffer).1 OPA2340(buffer).2 | length 59.5
  Top Layer w0.5: 186.256,195.668 188.576,195.719 ; 186.256,196.762 188.576,196.711 ; 186.489,195.695 188.576,196.711 ; 186.489,196.735 188.576,195.719 ; 188.307,196.307 188.849,197.866 ; 188.783,195.669 186.549,196.215 ; 188.783,196.761 186.549,196.215 ; 189.391,196.307 188.849,197.866 ; 500_2.2@203.904,197.458 204.343,198.374 ; 500_2.2@204.343,197.358 204.343,198.374 ; 500_2.2@204.782,197.458 204.343,198.374 ; 186.309,196.215 188.609,196.215 ; 186.309,196.215 188.576,196.711 ; 186.309,196.215 188.576,195.719 ; 186.309,196.215 188.849,196.215 ; 186.549,196.215 188.849,196.215 ; 188.609,196.215 186.375,195.669 188.609,196.215 ; 188.609,196.215 186.375,196.761 188.609,196.215 ; 188.849,196.215 188.849,197.866 ; 188.849,197.866 190.5,199.517 203.2,199.517 204.343,198.374
Net7407_2_1: 7407_2.1 LLC_SolenoidValve1.P$7 | length 23.2
  Top Layer w0.5: LLC_SolenoidValve1.P$7@291.465,166.878 295.656,166.878 297.053,168.275 297.053,173.355 298.704,175.006 ; LLC_SolenoidValve1.P$7@291.521,166.381 293.715,166.878 LLC_SolenoidValve1.P$7@291.521,167.375 ; 7407_2.1@299.855,174.469 298.704,175.006 ; 7407_2.1@299.855,175.543 298.704,175.006 ; 298.704,175.006 7407_2.1@299.974,175.006 298.704,175.006
Net7407_2_2: 7407_2.2 DSwitch.3 | length 28.4
  Top Layer w0.5: 7407_2.2@302.06,174.696 303.657,172.847 ; 7407_2.2@303.026,175.207 303.657,172.847 ; DSwitch.3@311.714,170.412 312.254,171.743 ; DSwitch.3@312.254,170.307 312.254,171.743 ; DSwitch.3@312.794,170.412 312.254,171.743 ; 302.514,173.99 7407_2.2@302.514,175.006 ; 302.514,173.99 301.985,174.857 302.514,173.99 ; 302.514,173.99 303.043,174.857 302.514,173.99 ; 302.514,173.99 303.657,172.847 ; 302.514,173.99 7407_2.2@302.514,175.006 ; 7407_2.2@302.514,175.006 303.657,172.847 ; 303.657,172.847 311.15,172.847 312.254,171.743
Net7407_2_3: 7407_2.3 LLC_SolenoidValve1.P$8 | length 34.5
  Top Layer w0.5: LLC_SolenoidValve1.P$8@291.465,169.418 294.005,169.418 295.529,170.942 295.529,173.863 298.323,176.657 304.419,176.657 ; LLC_SolenoidValve1.P$8@291.521,168.921 293.715,169.418 LLC_SolenoidValve1.P$8@291.521,169.915 ; 7407_2.3@304.516,174.891 304.419,176.657 ; 7407_2.3@305.53,175.281 304.419,176.657 ; 304.419,176.657 7407_2.3@305.054,175.006 ; 304.419,176.657 305.054,176.022 ; 7407_2.3@305.054,175.006 305.054,176.022 ; 7407_2.3@305.054,175.006 305.054,176.022 ; 305.054,176.022 305.583,175.155 305.054,176.022 ; 305.054,176.022 304.525,175.155 305.054,176.022
Net7407_2_4: 7407_2.4 DSwitch.6 | length 11.7
  Bottom Layer w0.5: DSwitch.6@304.101,170.444 304.634,171.411 ; DSwitch.6@304.634,170.307 304.634,171.411 ; DSwitch.6@305.167,170.444 304.634,171.411 ; 7407_2.4@307.053,174.907 307.594,173.482 ; 7407_2.4@307.594,175.006 307.594,173.482 ; 7407_2.4@308.135,174.907 307.594,173.482 ; 304.634,171.411 305.689,172.466 306.578,172.466 307.594,173.482
Net7407_2_5: 7407_2.5 LLC_SolenoidValve1.P$11 | length 27.6
  Top Layer w0.5: LLC_SolenoidValve1.P$11@291.465,177.038 292.989,177.038 ; LLC_SolenoidValve1.P$11@291.547,176.545 292.989,177.038 ; LLC_SolenoidValve1.P$11@291.547,177.531 292.989,177.038 ; 7407_2.5@309.593,175.105 310.134,176.53 ; 7407_2.5@310.134,175.006 310.134,176.53 ; 7407_2.5@310.675,175.105 310.134,176.53 ; 292.989,177.038 294.259,178.308 308.356,178.308 310.134,176.53
Net7407_2_6: 7407_2.6 DSwitch.11 | length 63.2
  Top Layer w0.5: DSwitch.11@304.095,162.798 304.634,164.045 ; DSwitch.11@304.634,162.687 304.634,164.045 ; DSwitch.11@305.173,162.798 304.634,164.045 ; 7407_2.6@312.133,175.105 312.674,176.53 ; 7407_2.6@312.674,175.006 312.674,176.53 ; 7407_2.6@313.215,175.105 312.674,176.53 ; v3@313.534,164.243 311.463,164.592 v3@313.534,164.941 ; v3(313.563,164.592) 305.181,164.592 304.634,164.045 ; v3@316.201,177.07 314.13,177.419 ; v3@316.201,177.768 314.13,177.419 ; 312.674,176.53 313.563,177.419 v3(316.23,177.419) 314.13,177.419
  Bottom Layer w0.5: v3(313.563,164.592) 319.913,164.592 320.421,165.1 320.421,175.641 318.643,177.419 v3(316.23,177.419) ; v3@313.592,164.243 315.663,164.592 v3@313.592,164.941 ; v3@316.259,177.07 318.33,177.419 v3@316.259,177.768
Net7407_2_8: 7407_2.8 DSwitch.15 | length 59.1
  Top Layer w0.5: DSwitch.15@314.383,163.053 316.289,164.778 ; 7407_2.8@314.677,182.507 315.214,181.356 ; DSwitch.15@315.273,162.417 316.289,164.778 ; 7407_2.8@315.751,182.507 315.214,181.356 ; v3@318.098,179.738 316.484,180.086 ; v3@318.098,180.434 316.484,180.086 ; v3@321.662,164.497 319.591,164.846 v3@321.662,165.195 ; v3(321.691,164.846) 316.357,164.846 314.794,163.283 DSwitch.15@314.794,162.687 316.289,164.778 ; 315.214,181.356 7407_2.8@315.214,182.626 315.214,181.356 ; 315.214,181.356 316.484,180.086 ; 316.484,180.086 v3(318.135,180.086) 316.484,180.086
  Bottom Layer w0.5: v3@317.907,179.821 319.796,178.425 v3@318.4,180.314 ; v3(318.135,180.086) 321.691,176.53 v3(321.691,164.846) ; v3@321.342,164.875 321.691,166.946 v3@322.04,164.875
Net7407_2_9: 7407_2.9 LLC_SolenoidValve1.P$12 | length 34.1
  Top Layer w0.5: LLC_SolenoidValve1.P$12@291.465,179.578 301.244,179.578 302.387,180.721 311.531,180.721 ; LLC_SolenoidValve1.P$12@291.521,179.081 293.715,179.578 LLC_SolenoidValve1.P$12@291.521,180.075 ; 7407_2.9@312.171,182.848 311.531,180.721 ; 7407_2.9@313.107,182.287 311.531,180.721 ; 311.531,180.721 7407_2.9@312.674,182.626 312.674,181.864 311.531,180.721
Net7407_3_1: 7407_3.1 LLC_SolenoidValve2.P$7 | length 33.1
  Top Layer w0.5: LLC_SolenoidValve2.P$7@291.119,228.669 293.613,229.605 ; LLC_SolenoidValve2.P$7@291.637,227.818 293.613,229.605 ; 7407_3.1@299.781,236.055 297.561,236.601 ; 7407_3.1@299.781,237.147 297.561,236.601 ; LLC_SolenoidValve2.P$7@291.338,228.219 292.227,228.219 ; LLC_SolenoidValve2.P$7@291.338,228.219 293.613,229.605 ; LLC_SolenoidValve2.P$7@291.338,228.219 292.227,228.219 ; 292.227,228.219 291.479,227.739 292.227,228.219 ; 292.227,228.219 291.479,228.699 292.227,228.219 ; 292.227,228.219 295.783,231.775 295.783,234.823 297.561,236.601 ; 297.561,236.601 7407_3.1@299.847,236.601 297.561,236.601
Net7407_3_2: 7407_3.2 DSwitch2.3 | length 23.8
  Top Layer w0.5: 7407_3.2@301.841,236.535 302.387,234.315 ; 7407_3.2@302.387,236.601 302.387,234.315 ; 7407_3.2@302.933,236.535 302.387,234.315 ; DSwitch2.3@311.583,230.075 312.127,231.941 ; DSwitch2.3@312.127,229.577 DSwitch2.3@312.127,229.997 312.127,231.941 ; DSwitch2.3@312.672,230.075 312.127,231.941 ; 302.387,234.315 303.282,233.42 310.648,233.42 312.127,231.941
Net7407_3_3: 7407_3.3 LLC_SolenoidValve2.P$8 | length 34.4
  Top Layer w0.5: LLC_SolenoidValve2.P$8@291.124,231.211 293.553,232.085 ; LLC_SolenoidValve2.P$8@291.635,230.357 293.553,232.085 ; 7407_3.3@304.393,236.733 304.927,237.744 ; 7407_3.3@304.927,236.601 304.927,237.744 ; 7407_3.3@305.461,236.733 304.927,237.744 ; LLC_SolenoidValve2.P$8@291.338,230.759 292.227,230.759 ; LLC_SolenoidValve2.P$8@291.338,230.759 293.553,232.085 ; LLC_SolenoidValve2.P$8@291.338,230.759 292.227,230.759 ; 292.227,230.759 291.479,230.279 292.227,230.759 ; 292.227,230.759 291.479,231.239 292.227,230.759 ; 292.227,230.759 294.132,232.664 294.132,235.712 296.799,238.379 304.292,238.379 304.927,237.744
Net7407_3_4: 7407_3.4 DSwitch2.6 | length 25
  Bottom Layer w0.5: DSwitch2.6@303.961,230.063 304.507,232.297 DSwitch2.6@305.053,230.063 ; DSwitch2.6@304.507,229.997 304.507,232.752 307.467,235.712 ; 7407_3.4@306.971,236.839 306.06,234.305 ; 7407_3.4@307.904,236.267 306.06,234.305 ; 306.06,234.305 7407_3.4@307.467,236.601 ; 307.467,235.712 7407_3.4@307.467,236.601 ; 307.467,235.712 306.944,236.431 307.467,235.712 ; 307.467,235.712 307.99,236.431 307.467,235.712 ; 307.467,235.712 7407_3.4@307.467,236.601
Net7407_3_5: 7407_3.5 LLC_SolenoidValve2.P$11 | length 28.9
  Top Layer w0.5: LLC_SolenoidValve2.P$11@291.338,238.379 293.751,238.379 295.021,239.649 308.483,239.649 310.007,238.125 ; LLC_SolenoidValve2.P$11@291.394,237.882 293.588,238.379 LLC_SolenoidValve2.P$11@291.394,238.876 ; 7407_3.5@309.466,236.7 310.007,238.125 ; 7407_3.5@310.007,236.601 310.007,238.125 ; 7407_3.5@310.548,236.7 310.007,238.125
Net7407_3_6: 7407_3.6 DSwitch2.11 | length 61.2
  Top Layer w0.5: DSwitch2.11@304.087,222.732 305.435,223.901 ; DSwitch2.11@305.015,222.167 305.435,223.901 ; v3@310.783,223.552 308.712,223.901 v3@310.783,224.25 ; v3(310.812,223.901) 305.435,223.901 ; 7407_3.6@312.005,236.693 312.547,238.252 ; 7407_3.6@312.547,236.601 312.547,238.252 ; 7407_3.6@313.089,236.693 312.547,238.252 ; v1@317.344,238.792 315.273,239.141 ; v1@317.344,239.49 315.273,239.141 ; 305.435,223.901 DSwitch2.11@304.507,222.377 304.507,222.973 305.435,223.901 ; 312.547,238.252 313.436,239.141 v1(317.373,239.141) 315.273,239.141
  Bottom Layer w0.5: v3(310.812,223.901) 312.166,223.901 ; v3@310.857,223.554 312.166,223.901 ; v3@310.857,224.248 312.166,223.901 ; v1(317.373,239.141) 318.262,239.141 ; v1@317.442,238.798 318.262,239.141 ; v1@317.442,239.484 318.262,239.141 ; 312.166,223.901 313.563,225.298 318.135,225.298 319.151,226.314 319.151,238.252 318.262,239.141
Net7407_3_8: 7407_3.8 DSwitch2.15 | length 58.2
  Top Layer w0.5: DSwitch2.15@314.134,222.514 314.667,223.481 ; DSwitch2.15@314.667,222.377 314.667,223.481 ; 7407_3.8@315.087,244.221 320.167,244.221 ; 7407_3.8@315.153,243.675 317.387,244.221 7407_3.8@315.153,244.767 ; DSwitch2.15@315.2,222.514 314.667,223.481 ; v3@321.389,225.855 320.675,224.282 ; v1@321.424,242.47 320.167,244.221 ; v1(321.691,242.697) 320.167,244.221 ; v1@321.918,242.964 320.167,244.221 ; v3@321.952,225.446 320.675,224.282 ; 314.667,223.481 315.468,224.282 320.675,224.282 ; 320.675,224.282 v3(321.691,225.679) 321.691,225.298 320.675,224.282
  Bottom Layer w0.5: v3@321.342,225.708 321.691,227.779 v3@322.04,225.708 ; v1@321.342,242.668 321.691,240.597 v1@322.04,242.668 ; v3(321.691,225.679) v1(321.691,242.697)
Net7407_3_9: 7407_3.9 LLC_SolenoidValve2.P$12 | length 31.7
  Top Layer w0.5: LLC_SolenoidValve2.P$12@291.338,240.919 311.023,240.919 312.547,242.443 ; LLC_SolenoidValve2.P$12@291.394,240.422 293.588,240.919 LLC_SolenoidValve2.P$12@291.394,241.416 ; 7407_3.9@312.004,244.136 312.547,242.443 ; 7407_3.9@312.547,244.221 312.547,242.443 ; 7407_3.9@313.09,244.136 312.547,242.443
Net7407_4_1: 7407_4.1 LLC_SolenoidValve3.P$7 | length 27
  Top Layer w0.5: LLC_SolenoidValve3.P$7@291.338,196.723 293.751,196.723 296.291,199.263 296.291,204.978 297.053,205.74 7407_4.1@299.847,205.74 297.547,205.74 ; LLC_SolenoidValve3.P$7@291.394,196.226 293.588,196.723 LLC_SolenoidValve3.P$7@291.394,197.22 ; 7407_4.1@299.781,205.194 297.547,205.74 ; 7407_4.1@299.781,206.286 297.547,205.74
Net7407_4_2: 7407_4.2 DSwitch3.3 | length 40.9
  Top Layer w0.5: 7407_4.2@301.841,205.672 302.387,203.518 ; 7407_4.2@302.387,205.74 302.387,203.518 ; 7407_4.2@302.933,205.672 302.387,203.518 ; v3@303.387,202.88 302.387,203.518 ; v3@303.573,203.547 302.387,203.518 ; v3(307.975,203.2) 310.896,203.2 312.127,201.969 ; v3@308.004,202.851 310.075,203.2 v3@308.004,203.549 ; DSwitch3.3@311.592,200.915 312.127,201.969 ; DSwitch3.3@312.127,200.787 312.127,201.969 ; DSwitch3.3@312.662,200.915 312.127,201.969 ; 302.387,203.518 v3(303.53,203.2) ; 302.387,203.518 302.705,203.2 ; 302.705,203.2 v3(303.53,203.2) ; 302.705,203.2 303.456,203.542 302.705,203.2 ; 302.705,203.2 303.456,202.858 302.705,203.2 ; 302.705,203.2 v3(303.53,203.2)
  Bottom Layer w0.5: v3(303.53,203.2) v3(307.975,203.2) ; v3@303.559,202.851 305.63,203.2 v3@303.559,203.549 ; v3@307.946,202.851 305.875,203.2 v3@307.946,203.549
Net7407_4_3: 7407_4.3 LLC_SolenoidValve3.P$8 | length 27.5
  Top Layer w0.5: LLC_SolenoidValve3.P$8@291.338,199.263 293.37,199.263 ; LLC_SolenoidValve3.P$8@291.4,198.767 293.37,199.263 ; LLC_SolenoidValve3.P$8@291.4,199.759 293.37,199.263 ; 7407_4.3@304.393,205.872 304.927,206.883 ; 7407_4.3@304.927,205.74 304.927,206.883 ; 7407_4.3@305.461,205.872 304.927,206.883 ; 293.37,199.263 294.767,200.66 294.767,205.232 297.18,207.645 304.165,207.645 304.927,206.883
Net7407_4_4: 7407_4.4 DSwitch3.6 | length 16.9
  Top Layer w0.5: DSwitch3.6@303.969,200.903 304.507,202.096 ; DSwitch3.6@304.507,200.787 304.507,202.096 ; DSwitch3.6@305.045,200.903 304.507,202.096 ; 7407_4.4@306.985,206.005 305.94,203.529 ; 7407_4.4@307.885,205.383 305.94,203.529 ; 304.507,202.096 307.467,205.056 7407_4.4@307.467,205.74 305.94,203.529
Net7407_4_5: 7407_4.5 LLC_SolenoidValve3.P$11 | length 23.1
  Top Layer w0.5: LLC_SolenoidValve3.P$11@291.338,206.883 LLC_SolenoidValve3.P$11@291.611,207.156 ; 292.735,206.883 294.386,208.534 308.61,208.534 310.007,207.137 ; 7407_4.5@309.468,205.848 310.007,207.137 ; 7407_4.5@310.007,205.74 310.007,207.137 ; 7407_4.5@310.546,205.848 310.007,207.137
